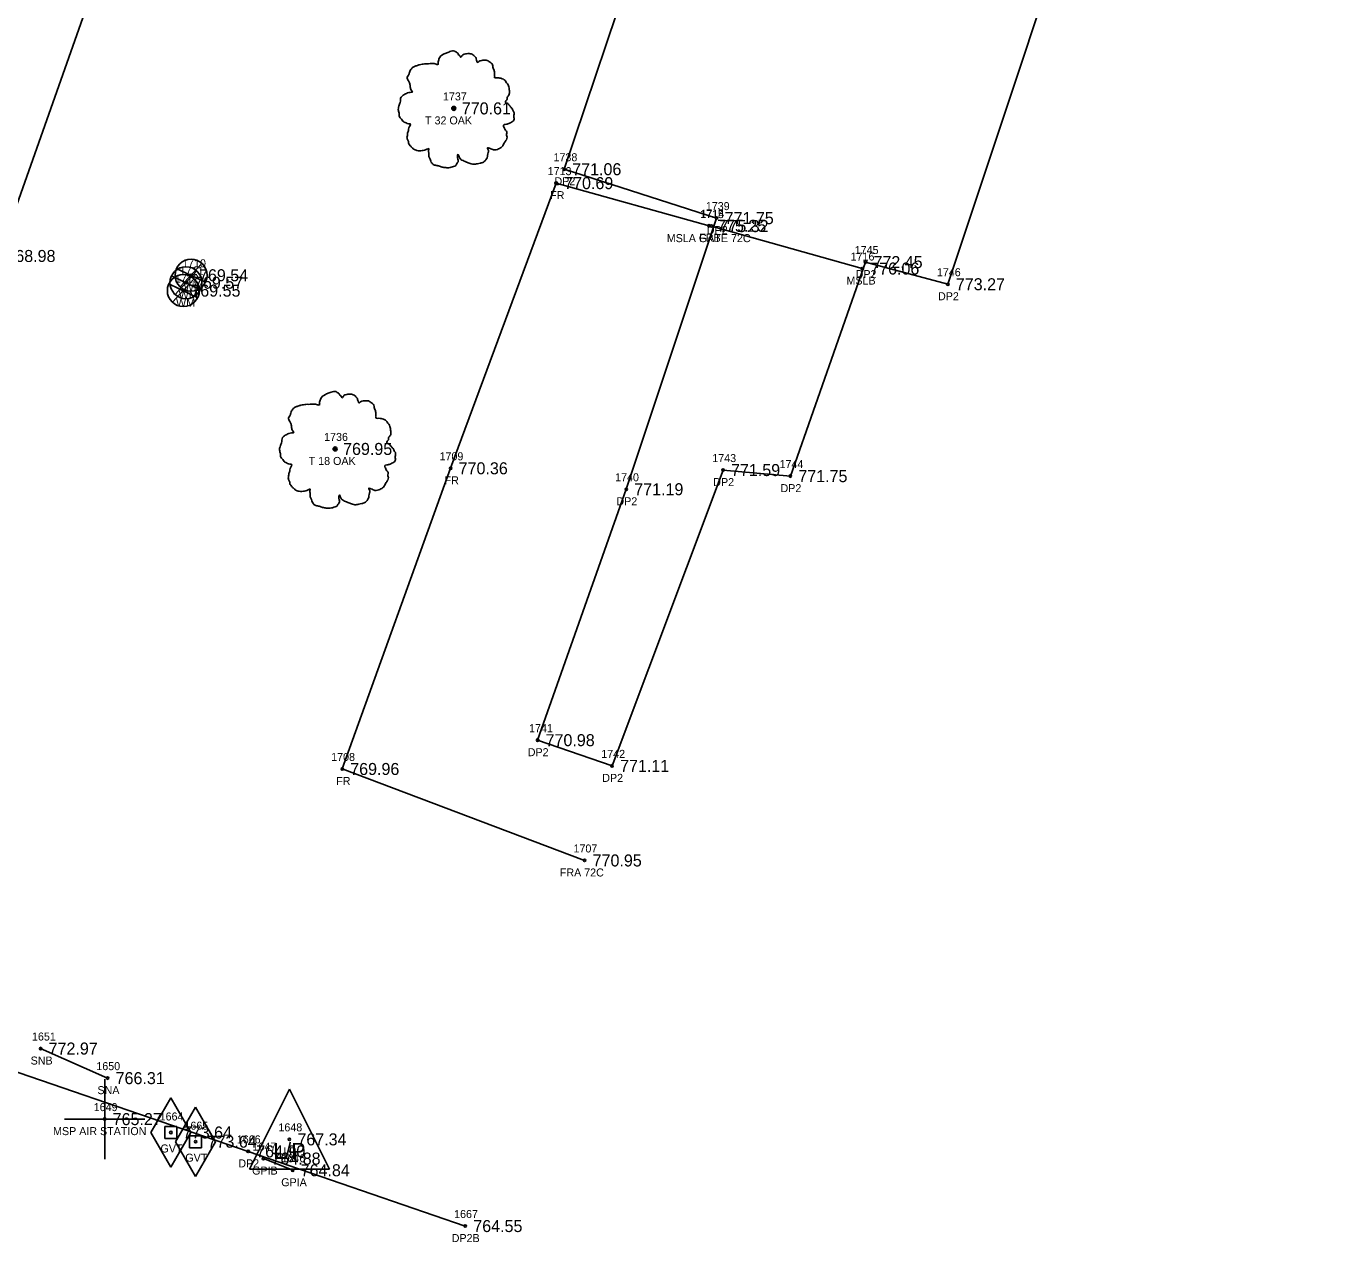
# Model space of a CAD drawing. Extents: x 1736563 to 1738032, y 1150548 to 1154248.
# Drawn here: x 1737815.3 to 1737979.7, y 1153640.2 to 1153793.3 of the extents above; entities that cross this region are included whole.
import ezdxf

# ---------------------------------------------------------------- set-up
doc = ezdxf.new("R2010")
doc.units = 0
for name, color, linetype in [('RD_EX_BldgApp', 7, 'Continuous'), ('RD_EX_BldgApp_txCode', 7, 'Continuous'), ('RD_EX_Driveway', 7, 'Continuous'), ('RD_EX_Driveway_txCode', 7, 'Continuous'), ('RD_EX_Fence_Other', 7, 'Continuous'), ('RD_EX_Fence_Other_txCode', 7, 'Continuous'), ('RD_EX_Misc', 7, 'Continuous'), ('RD_EX_Misc_txCode', 7, 'Continuous'), ('RD_EX_Road', 7, 'Continuous'), ('RD_EX_TX_BldgApp_ELEV', 7, 'Continuous'), ('RD_EX_TX_Driveway_ELEV', 7, 'Continuous'), ('RD_EX_TX_Fence_Other_ELEV', 7, 'Continuous'), ('RD_EX_TX_Misc_ELEV', 7, 'Continuous'), ('RD_EX_TX_Road_ELEV', 7, 'Continuous'), ('RD_EX_TX_UT_ELEV', 7, 'Continuous'), ('RD_EX_TX_VEG_ELEV', 7, 'Continuous'), ('RD_EX_UT', 7, 'Continuous'), ('RD_EX_UT_txCode', 7, 'Continuous'), ('RD_EX_VEG', 7, 'Continuous'), ('RD_EX_VEG_txCode', 7, 'Continuous'), ('RD_SMD_Locator', 7, 'Continuous')]:
    doc.layers.add(name, color=color, linetype=linetype)

msp = doc.modelspace()

# ---------------------------------------------------------------- linework, layer by layer
at = {"layer": 'RD_EX_BldgApp'}
for p, q in [((1737825.51, 1153661.91), (1737817.14, 1153665.61)), ((1737848.63, 1153650.4), (1737844.98, 1153651.86))]:
    msp.add_line(p, q, dxfattribs=at)
at = {"layer": 'RD_EX_Driveway'}
for points in [[(1737914.37, 1153858.93), (1737922.44, 1153844.68), (1737915.71, 1153827.95), (1737900.96, 1153830.18), (1737882.56, 1153775.48), (1737901.6, 1153769.37), (1737890.31, 1153735.49), (1737879.23, 1153704.14), (1737888.54, 1153700.93), (1737902.4, 1153737.89), (1737910.81, 1153737.13), (1737920.2, 1153763.88), (1737930.49, 1153761.11), (1737950.72, 1153821.93), (1737970.68, 1153812.97), (1737979.7, 1153847.95)], [(1737786.15, 1153689.96), (1737791.25, 1153672.63), (1737795.21, 1153669.68), (1737803.88, 1153667.15), (1737803.51, 1153666.31), (1737843.07, 1153652.76), (1737870.2, 1153643.43)]]:
    msp.add_lwpolyline(points, dxfattribs=at)
at = {"layer": 'RD_EX_Fence_Other'}
msp.add_lwpolyline([(1737885.11, 1153689.11), (1737854.82, 1153700.54), (1737868.37, 1153738.11), (1737881.55, 1153773.74), (1737900.66, 1153768.41)], dxfattribs=at)
at = {"layer": 'RD_EX_Misc'}
for p, q in [((1737900.96, 1153768.37), (1737919.79, 1153763.07)), ((1737825.14, 1153651.79), (1737825.14, 1153661.79)), ((1737820.14, 1153656.79), (1737830.14, 1153656.79))]:
    msp.add_line(p, q, dxfattribs=at)
at = {"layer": 'RD_EX_Road'}
msp.add_lwpolyline([(1737767.23, 1153635.63), (1737779.62, 1153670.7), (1737786.15, 1153689.96), (1737811.86, 1153764.64), (1737841.92, 1153849.66), (1737845.41, 1153858.54), (1737858.39, 1153893.35), (1737872.4, 1153934.23), (1737879.38, 1153953.57), (1737912.95, 1154048.07), (1737946.82, 1154144.4)], dxfattribs=at)
at = {"layer": 'RD_EX_UT'}
for p, q in [((1737833.47, 1153762.14), (1737837.1, 1153760.42)), ((1737833.95, 1153759.84), (1737836.62, 1153762.74)), ((1737834.09, 1153763.07), (1737837.72, 1153761.36)), ((1737834.58, 1153760.77), (1737837.24, 1153763.67)), ((1737833.14, 1153761.14), (1737836.77, 1153759.43)), ((1737833.62, 1153758.85), (1737836.28, 1153761.74)), ((1737843.22, 1153650.53), (1737848.22, 1153660.53)), ((1737848.22, 1153660.53), (1737853.22, 1153650.53)), ((1737830.91, 1153655.12), (1737833.41, 1153659.45)), ((1737833.41, 1153659.45), (1737835.91, 1153655.12)), ((1737834, 1153653.97), (1737836.5, 1153658.3)), ((1737836.5, 1153658.3), (1737839, 1153653.97)), ((1737834.16, 1153655.87), (1737832.66, 1153655.87)), ((1737832.66, 1153655.87), (1737832.66, 1153654.37)), ((1737834.16, 1153654.37), (1737834.16, 1153655.87)), ((1737830.91, 1153655.12), (1737833.41, 1153650.79)), ((1737832.66, 1153654.37), (1737834.16, 1153654.37)), ((1737833.41, 1153650.79), (1737835.91, 1153655.12)), ((1737834, 1153653.97), (1737836.5, 1153649.64)), ((1737837.25, 1153654.72), (1737835.75, 1153654.72)), ((1737835.75, 1153654.72), (1737835.75, 1153653.22)), ((1737836.5, 1153649.64), (1737839, 1153653.97)), ((1737837.25, 1153653.22), (1737837.25, 1153654.72)), ((1737835.75, 1153653.22), (1737837.25, 1153653.22)), ((1737843.22, 1153650.53), (1737853.22, 1153650.53))]:
    msp.add_line(p, q, dxfattribs=at)
for centre, radius in [((1737835.93, 1153762.23), 2), ((1737834.97, 1153760.31), 2), ((1737835.3, 1153761.3), 2), ((1737833.41, 1153655.12), 0.15), ((1737836.5, 1153653.97), 0.15)]:
    msp.add_circle(centre, radius, dxfattribs=at)
at = {"layer": 'RD_EX_VEG'}
for centre, radius in [((1737868.76, 1153783.08), 0.25), ((1737868.74, 1153783.06), 0.0001), ((1737853.93, 1153740.53), 0.25), ((1737853.92, 1153740.51), 0.0001)]:
    msp.add_circle(centre, radius, dxfattribs=at)
for points in [[(1737868.89, 1153790.24), (1737868.59, 1153790.27), (1737868.26, 1153790.17), (1737868.01, 1153790.07), (1737867.79, 1153789.99), (1737867.56, 1153789.89), (1737867.26, 1153789.72), (1737867.04, 1153789.52), (1737866.91, 1153789.27), (1737866.86, 1153789.04), (1737866.81, 1153788.77), (1737866.81, 1153788.59), (1737866.69, 1153788.57), (1737866.54, 1153788.59), (1737866.29, 1153788.67), (1737866.04, 1153788.67), (1737865.79, 1153788.67), (1737865.44, 1153788.64), (1737865.09, 1153788.64), (1737864.82, 1153788.59), (1737864.49, 1153788.54), (1737864.12, 1153788.42), (1737863.77, 1153788.29), (1737863.47, 1153788.04), (1737863.22, 1153787.57), (1737863.09, 1153787.22), (1737862.94, 1153786.97), (1737863.09, 1153786.52), (1737863.27, 1153786.17), (1737863.29, 1153785.97), (1737863.37, 1153785.55), (1737863.47, 1153785.32), (1737863.59, 1153785.12), (1737863.52, 1153785.1), (1737863.14, 1153785.05), (1737862.84, 1153784.95), (1737862.42, 1153784.72), (1737862.19, 1153784.5), (1737862.09, 1153784.17), (1737862.07, 1153783.82), (1737861.97, 1153783.62), (1737861.89, 1153783.35), (1737861.87, 1153783.27), (1737861.82, 1153782.95), (1737861.92, 1153782.5), (1737861.94, 1153782.15), (1737862.07, 1153781.92), (1737862.22, 1153781.75), (1737862.39, 1153781.5), (1737862.79, 1153781.27), (1737863.12, 1153781.17), (1737863.32, 1153781.15), (1737863.14, 1153780.65), (1737863.09, 1153780.3), (1737862.97, 1153779.9), (1737862.97, 1153779.82), (1737862.92, 1153779.35), (1737863.07, 1153779.02), (1737863.14, 1153778.65), (1737863.32, 1153778.42), (1737863.59, 1153778.12), (1737863.92, 1153777.9), (1737864.42, 1153777.77), (1737864.82, 1153777.8), (1737865.39, 1153777.97), (1737865.64, 1153778.05), (1737865.62, 1153777.87), (1737865.64, 1153777.5), (1737865.64, 1153777.07), (1737865.79, 1153776.75), (1737865.89, 1153776.47), (1737866.04, 1153776.22), (1737866.37, 1153776), (1737866.76, 1153775.92), (1737867.19, 1153775.77), (1737867.64, 1153775.7), (1737868.14, 1153775.67), (1737868.74, 1153775.82), (1737869.01, 1153775.95), (1737869.11, 1153776.12), (1737869.31, 1153776.5), (1737869.26, 1153776.72), (1737869.29, 1153777.32), (1737869.39, 1153777.15), (1737869.56, 1153776.8), (1737870.06, 1153776.5), (1737870.46, 1153776.32), (1737870.94, 1153776.17), (1737871.24, 1153776.1), (1737871.71, 1153776.17), (1737872.09, 1153776.25), (1737872.46, 1153776.37), (1737872.76, 1153776.65), (1737872.94, 1153776.92), (1737872.99, 1153777.2), (1737873.06, 1153777.57), (1737873.11, 1153777.75)], [(1737873.11, 1153777.75), (1737873.04, 1153777.92), (1737872.99, 1153778.17), (1737873.06, 1153778.15), (1737873.24, 1153778.1), (1737873.51, 1153777.97), (1737873.74, 1153777.9), (1737874.06, 1153777.92), (1737874.34, 1153778.02), (1737874.79, 1153778.3), (1737875.06, 1153778.77), (1737875.34, 1153779.17), (1737875.41, 1153779.5), (1737875.36, 1153779.72), (1737875.34, 1153780.22), (1737875.14, 1153780.47), (1737875.09, 1153780.6), (1737874.99, 1153781), (1737875.06, 1153781.05), (1737875.34, 1153781.1), (1737875.71, 1153781.22), (1737875.99, 1153781.35), (1737876.21, 1153781.52), (1737876.29, 1153781.75), (1737876.26, 1153782.15), (1737876.31, 1153782.55), (1737876.24, 1153782.7), (1737876.14, 1153782.85), (1737876.06, 1153783.05), (1737875.91, 1153783.2), (1737875.81, 1153783.35), (1737875.71, 1153783.45), (1737875.59, 1153783.6), (1737875.41, 1153783.72), (1737875.26, 1153783.77), (1737875.21, 1153783.92), (1737875.36, 1153784.12), (1737875.41, 1153784.22), (1737875.44, 1153784.45), (1737875.66, 1153784.8), (1737875.71, 1153785.2), (1737875.66, 1153785.62), (1737875.61, 1153785.9), (1737875.46, 1153786.17), (1737875.26, 1153786.42), (1737875.14, 1153786.6), (1737874.96, 1153786.72), (1737874.64, 1153786.84), (1737874.39, 1153786.89), (1737874.04, 1153786.89), (1737873.84, 1153786.94), (1737873.86, 1153786.99), (1737873.86, 1153787.14), (1737873.86, 1153787.42), (1737873.79, 1153787.87), (1737873.64, 1153788.37), (1737873.64, 1153788.39), (1737873.54, 1153788.64), (1737873.31, 1153788.84), (1737873.14, 1153788.94), (1737872.94, 1153789.07), (1737872.69, 1153789.09), (1737872.39, 1153789.09), (1737872.11, 1153789.04), (1737871.91, 1153788.94), (1737871.74, 1153788.82), (1737871.66, 1153788.97), (1737871.56, 1153789.27), (1737871.51, 1153789.42), (1737871.36, 1153789.59), (1737871.14, 1153789.79), (1737870.69, 1153789.92), (1737870.06, 1153789.84), (1737869.76, 1153789.64), (1737869.61, 1153789.47), (1737869.56, 1153789.59), (1737869.36, 1153789.79), (1737869.26, 1153789.97), (1737869.09, 1153790.09), (1737868.94, 1153790.19), (1737868.84, 1153790.24)], [(1737854.07, 1153747.7), (1737853.77, 1153747.72), (1737853.44, 1153747.62), (1737853.19, 1153747.52), (1737852.97, 1153747.45), (1737852.74, 1153747.35), (1737852.44, 1153747.17), (1737852.22, 1153746.97), (1737852.09, 1153746.72), (1737852.04, 1153746.5), (1737851.99, 1153746.22), (1737851.99, 1153746.05), (1737851.87, 1153746.02), (1737851.72, 1153746.05), (1737851.47, 1153746.12), (1737851.22, 1153746.12), (1737850.97, 1153746.12), (1737850.62, 1153746.1), (1737850.27, 1153746.1), (1737849.99, 1153746.05), (1737849.67, 1153746), (1737849.29, 1153745.87), (1737848.94, 1153745.75), (1737848.64, 1153745.5), (1737848.39, 1153745.02), (1737848.27, 1153744.67), (1737848.12, 1153744.42), (1737848.27, 1153743.97), (1737848.44, 1153743.62), (1737848.47, 1153743.42), (1737848.54, 1153743), (1737848.64, 1153742.78), (1737848.77, 1153742.58), (1737848.69, 1153742.55), (1737848.32, 1153742.5), (1737848.02, 1153742.4), (1737847.59, 1153742.18), (1737847.37, 1153741.95), (1737847.27, 1153741.63), (1737847.24, 1153741.28), (1737847.14, 1153741.08), (1737847.07, 1153740.8), (1737847.04, 1153740.73), (1737846.99, 1153740.4), (1737847.09, 1153739.95), (1737847.12, 1153739.6), (1737847.24, 1153739.38), (1737847.39, 1153739.2), (1737847.57, 1153738.95), (1737847.97, 1153738.73), (1737848.29, 1153738.63), (1737848.49, 1153738.6), (1737848.32, 1153738.1), (1737848.27, 1153737.75), (1737848.14, 1153737.35), (1737848.14, 1153737.28), (1737848.09, 1153736.8), (1737848.24, 1153736.48), (1737848.32, 1153736.1), (1737848.49, 1153735.88), (1737848.77, 1153735.58), (1737849.09, 1153735.35), (1737849.59, 1153735.23), (1737849.99, 1153735.25), (1737850.57, 1153735.43), (1737850.82, 1153735.5), (1737850.79, 1153735.33), (1737850.82, 1153734.95), (1737850.82, 1153734.53), (1737850.97, 1153734.2), (1737851.07, 1153733.93), (1737851.22, 1153733.68), (1737851.54, 1153733.45), (1737851.94, 1153733.38), (1737852.37, 1153733.23), (1737852.82, 1153733.15), (1737853.32, 1153733.13), (1737853.92, 1153733.28), (1737854.19, 1153733.4), (1737854.29, 1153733.58), (1737854.49, 1153733.95), (1737854.44, 1153734.18), (1737854.47, 1153734.78), (1737854.57, 1153734.6), (1737854.74, 1153734.25), (1737855.24, 1153733.95), (1737855.64, 1153733.78), (1737856.11, 1153733.63), (1737856.41, 1153733.55), (1737856.89, 1153733.63), (1737857.26, 1153733.7), (1737857.64, 1153733.83), (1737857.94, 1153734.1), (1737858.11, 1153734.38), (1737858.16, 1153734.65), (1737858.24, 1153735.03), (1737858.29, 1153735.2)], [(1737858.29, 1153735.2), (1737858.21, 1153735.38), (1737858.16, 1153735.63), (1737858.24, 1153735.6), (1737858.41, 1153735.55), (1737858.69, 1153735.43), (1737858.91, 1153735.35), (1737859.24, 1153735.38), (1737859.51, 1153735.48), (1737859.96, 1153735.75), (1737860.24, 1153736.23), (1737860.51, 1153736.63), (1737860.59, 1153736.95), (1737860.54, 1153737.18), (1737860.51, 1153737.68), (1737860.31, 1153737.93), (1737860.26, 1153738.05), (1737860.16, 1153738.45), (1737860.24, 1153738.5), (1737860.51, 1153738.55), (1737860.89, 1153738.68), (1737861.16, 1153738.8), (1737861.39, 1153738.98), (1737861.46, 1153739.2), (1737861.44, 1153739.6), (1737861.49, 1153740), (1737861.41, 1153740.15), (1737861.31, 1153740.3), (1737861.24, 1153740.5), (1737861.09, 1153740.65), (1737860.99, 1153740.8), (1737860.89, 1153740.9), (1737860.76, 1153741.05), (1737860.59, 1153741.18), (1737860.44, 1153741.23), (1737860.39, 1153741.38), (1737860.54, 1153741.58), (1737860.59, 1153741.68), (1737860.61, 1153741.9), (1737860.84, 1153742.25), (1737860.89, 1153742.65), (1737860.84, 1153743.07), (1737860.79, 1153743.35), (1737860.64, 1153743.62), (1737860.44, 1153743.87), (1737860.31, 1153744.05), (1737860.14, 1153744.17), (1737859.81, 1153744.3), (1737859.56, 1153744.35), (1737859.21, 1153744.35), (1737859.01, 1153744.4), (1737859.04, 1153744.45), (1737859.04, 1153744.6), (1737859.04, 1153744.87), (1737858.96, 1153745.32), (1737858.81, 1153745.82), (1737858.81, 1153745.85), (1737858.71, 1153746.1), (1737858.49, 1153746.3), (1737858.31, 1153746.4), (1737858.11, 1153746.52), (1737857.86, 1153746.55), (1737857.56, 1153746.55), (1737857.29, 1153746.5), (1737857.09, 1153746.4), (1737856.91, 1153746.27), (1737856.84, 1153746.42), (1737856.74, 1153746.72), (1737856.69, 1153746.87), (1737856.54, 1153747.05), (1737856.31, 1153747.25), (1737855.86, 1153747.37), (1737855.24, 1153747.3), (1737854.94, 1153747.1), (1737854.79, 1153746.92), (1737854.74, 1153747.05), (1737854.54, 1153747.25), (1737854.44, 1153747.42), (1737854.27, 1153747.55), (1737854.12, 1153747.65), (1737854.02, 1153747.7)]]:
    msp.add_spline(points, degree=3, dxfattribs=at)
at = {"layer": 'RD_SMD_Locator'}
for centre in [(1737868.76, 1153783.08), (1737882.56, 1153775.48), (1737881.55, 1153773.74), (1737901.6, 1153769.37), (1737900.66, 1153768.41), (1737900.96, 1153768.37), (1737920.2, 1153763.88), (1737835.93, 1153762.23), (1737919.79, 1153763.07), (1737835.3, 1153761.3), (1737930.49, 1153761.11), (1737834.97, 1153760.31), (1737853.93, 1153740.53), (1737868.37, 1153738.11), (1737902.4, 1153737.89), (1737910.81, 1153737.13), (1737890.31, 1153735.49), (1737879.23, 1153704.14), (1737854.82, 1153700.54), (1737888.54, 1153700.93), (1737885.11, 1153689.11), (1737817.14, 1153665.61), (1737825.51, 1153661.91), (1737825.14, 1153656.79), (1737848.22, 1153654.26), (1737843.07, 1153652.76), (1737844.98, 1153651.86), (1737848.63, 1153650.4), (1737870.2, 1153643.43)]:
    msp.add_circle(centre, 0.15, dxfattribs=at)

# ---------------------------------------------------------------- texts
at = {"layer": 'RD_EX_BldgApp_txCode'}
for s, p in [('1651', (1737816.06, 1153666.61)), ('SNB', (1737815.89, 1153663.61)), ('1650', (1737824.1, 1153662.91)), ('SNA', (1737824.24, 1153659.91)), ('1647', (1737843.61, 1153652.86)), ('1646', (1737847.24, 1153651.4)), ('GPIB', (1737843.56, 1153649.86)), ('GPIA', (1737847.2, 1153648.4))]:
    msp.add_text(s, height=1, dxfattribs=at).set_placement(p)
at = {"layer": 'RD_EX_Driveway_txCode'}
for s, p in [('1738', (1737881.22, 1153776.48)), ('DP2', (1737881.34, 1153773.48)), ('1739', (1737900.25, 1153770.37)), ('DP2', (1737900.37, 1153767.37)), ('1745', (1737918.85, 1153764.88)), ('DP2', (1737918.97, 1153761.88)), ('1746', (1737929.12, 1153762.11)), ('DP2', (1737929.26, 1153759.11)), ('1743', (1737901.06, 1153738.89)), ('1744', (1737909.46, 1153738.13)), ('1740', (1737888.92, 1153736.49)), ('DP2', (1737901.18, 1153735.89)), ('DP2', (1737909.58, 1153735.13)), ('DP2', (1737889.08, 1153733.49)), ('1741', (1737878.16, 1153705.14)), ('DP2', (1737878, 1153702.14)), ('1742', (1737887.19, 1153701.93)), ('DP2', (1737887.31, 1153698.93)), ('1666', (1737841.65, 1153653.76)), ('DP2', (1737841.84, 1153650.76)), ('1667', (1737868.8, 1153644.43)), ('DP2B', (1737868.5, 1153641.43))]:
    msp.add_text(s, height=1, dxfattribs=at).set_placement(p)
at = {"layer": 'RD_EX_Fence_Other_txCode'}
for s, p in [('1713', (1737880.49, 1153774.74)), ('FR', (1737880.8, 1153771.74)), ('1714', (1737899.59, 1153769.41)), ('FRB', (1737899.43, 1153766.41)), ('1709', (1737866.98, 1153739.11)), ('FR', (1737867.61, 1153736.11)), ('1708', (1737853.44, 1153701.54)), ('FR', (1737854.07, 1153698.54)), ('1707', (1737883.72, 1153690.11)), ('FRA 72C', (1737882.01, 1153687.11))]:
    msp.add_text(s, height=1, dxfattribs=at).set_placement(p)
at = {"layer": 'RD_EX_Misc_txCode'}
for s, p in [('1715', (1737899.53, 1153769.37)), ('MSLA GATE 72C', (1737895.37, 1153766.37)), ('1716', (1737918.34, 1153764.07)), ('MSLB', (1737917.82, 1153761.07)), ('1649', (1737823.77, 1153657.79)), ('MSP AIR STATION', (1737818.69, 1153654.79))]:
    msp.add_text(s, height=1, dxfattribs=at).set_placement(p)
at = {"layer": 'RD_EX_TX_BldgApp_ELEV'}
for s, p in [('772.97', (1737818.14, 1153664.86)), ('766.31', (1737826.51, 1153661.16)), ('764.88', (1737845.98, 1153651.11)), ('764.84', (1737849.63, 1153649.65))]:
    msp.add_text(s, height=1.5, dxfattribs=at).set_placement(p)
at = {"layer": 'RD_EX_TX_Driveway_ELEV'}
for s, p in [('771.06', (1737883.56, 1153774.73)), ('771.75', (1737902.6, 1153768.62)), ('772.45', (1737921.2, 1153763.13)), ('773.27', (1737931.49, 1153760.36)), ('771.59', (1737903.4, 1153737.14)), ('771.75', (1737911.81, 1153736.38)), ('771.19', (1737891.31, 1153734.74)), ('770.98', (1737880.23, 1153703.39)), ('771.11', (1737889.54, 1153700.18)), ('764.90', (1737844.07, 1153652.01)), ('764.55', (1737871.2, 1153642.68))]:
    msp.add_text(s, height=1.5, dxfattribs=at).set_placement(p)
at = {"layer": 'RD_EX_TX_Fence_Other_ELEV'}
for s, p in [('770.69', (1737882.55, 1153772.99)), ('775.25', (1737901.66, 1153767.66)), ('770.36', (1737869.37, 1153737.36)), ('769.96', (1737855.82, 1153699.79)), ('770.95', (1737886.11, 1153688.36))]:
    msp.add_text(s, height=1.5, dxfattribs=at).set_placement(p)
at = {"layer": 'RD_EX_TX_Misc_ELEV'}
for s, p in [('775.32', (1737901.96, 1153767.62)), ('776.06', (1737920.79, 1153762.32)), ('765.27', (1737826.14, 1153656.04))]:
    msp.add_text(s, height=1.5, dxfattribs=at).set_placement(p)
at = {"layer": 'RD_EX_TX_Road_ELEV'}
msp.add_text('768.98', height=1.5, dxfattribs=at).set_placement((1737812.86, 1153763.89))
at = {"layer": 'RD_EX_TX_UT_ELEV'}
for s, p in [('769.54', (1737836.93, 1153761.48)), ('769.55', (1737835.97, 1153759.56)), ('769.57', (1737836.3, 1153760.55)), ('773.64', (1737834.91, 1153654.37)), ('773.64', (1737838, 1153653.22)), ('767.34', (1737849.22, 1153653.51))]:
    msp.add_text(s, height=1.5, dxfattribs=at).set_placement(p)
at = {"layer": 'RD_EX_TX_VEG_ELEV'}
for s, p in [('770.61', (1737869.76, 1153782.33)), ('769.95', (1737854.93, 1153739.78))]:
    msp.add_text(s, height=1.5, dxfattribs=at).set_placement(p)
at = {"layer": 'RD_EX_UT'}
msp.add_text('L/P', height=2, dxfattribs=at).set_placement((1737846.21, 1153651.82))
at = {"layer": 'RD_EX_UT_txCode'}
for s, p in [('1710', (1737834.82, 1153763.23)), ('1712', (1737833.91, 1153761.31)), ('1711', (1737834.52, 1153762.3)), ('WM', (1737835.02, 1153760.23)), ('WM', (1737834.06, 1153758.31)), ('WM', (1737834.39, 1153759.3)), ('1664', (1737832.01, 1153656.62)), ('1665', (1737835.11, 1153655.47)), ('1648', (1737846.85, 1153655.26)), ('GVT', (1737832.12, 1153652.62)), ('GVT', (1737835.22, 1153651.47)), ('LP', (1737847.46, 1153652.26))]:
    msp.add_text(s, height=1, dxfattribs=at).set_placement(p)
at = {"layer": 'RD_EX_VEG_txCode'}
for s, p in [('1737', (1737867.41, 1153784.08)), ('T 32 OAK', (1737865.17, 1153781.08)), ('1736', (1737852.56, 1153741.53)), ('T 18 OAK', (1737850.63, 1153738.53))]:
    msp.add_text(s, height=1, dxfattribs=at).set_placement(p)

doc.saveas('drawing.dxf')
